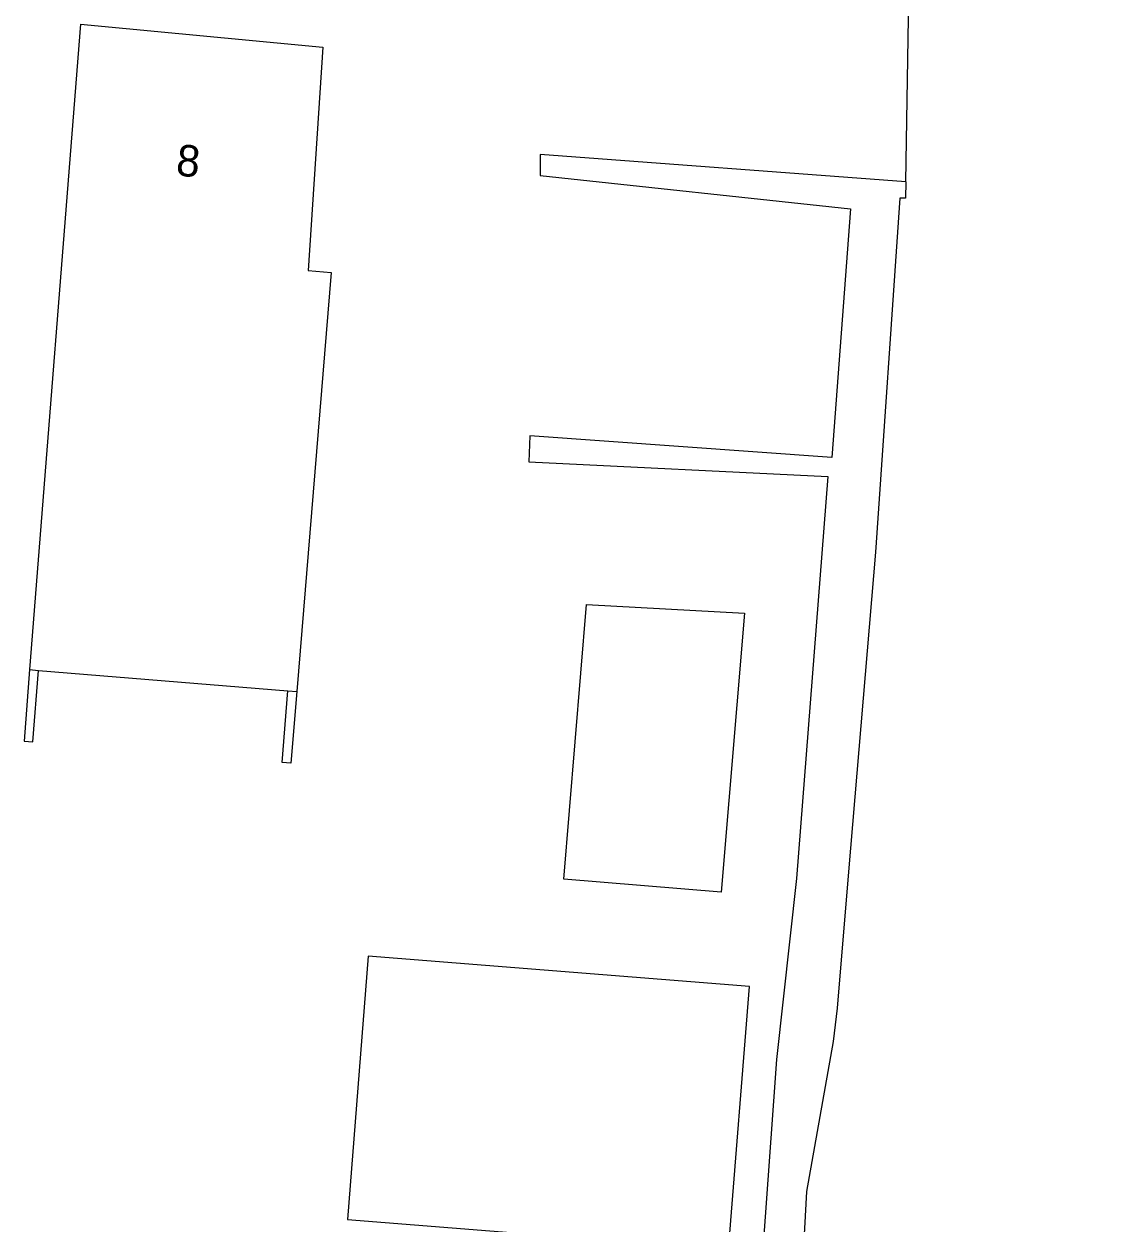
# Model space of a CAD drawing. Extents: x 137000 to 140001, y 403500 to 406000.
# Drawn here: x 138036.33 to 138070.55, y 405497.78 to 405535.89 of the extents above; entities that cross this region are included whole.
import ezdxf

# ---------------------------------------------------------------- set-up
doc = ezdxf.new("R2010")
doc.units = 0
for name, color, linetype in [('gg-afsc-muur', 7, 'Continuous'), ('gg-anno-huisnummerreeks BGT', 7, 'Continuous'), ('gg-bbg-bijgebouw', 7, 'Continuous'), ('gg-bbg-hoofdgebouw', 7, 'Continuous'), ('gg-knt-bronhoudergrens', 7, 'Continuous'), ('gt-grn-vlakafsluiter', 7, 'Continuous')]:
    doc.layers.add(name, color=color, linetype=linetype)

msp = doc.modelspace()

# ---------------------------------------------------------------- linework, layer by layer
at = {"layer": 'gg-afsc-muur'}
for points in [[(138036.508, 405515.388), (138036.329, 405513.115), (138036.608, 405513.093), (138036.787, 405515.365)], [(138044.987, 405514.69), (138044.8, 405512.418), (138044.521, 405512.441), (138044.708, 405514.713)]]:
    msp.add_lwpolyline(points, dxfattribs=at)
at = {"layer": 'gg-bbg-bijgebouw'}
for points in [[(138054.184, 405517.454), (138059.208, 405517.181), (138058.466, 405508.321), (138053.463, 405508.735), (138054.184, 405517.454)], [(138047.26, 405506.291), (138046.594, 405497.929), (138058.694, 405496.965), (138059.36, 405505.327), (138047.26, 405506.291)]]:
    msp.add_lwpolyline(points, dxfattribs=at)
at = {"layer": 'gg-bbg-hoofdgebouw'}
for p, q in [((138038.12, 405535.891), (138036.508, 405515.388)), ((138046.082, 405528.001), (138044.987, 405514.69)), ((138036.508, 405515.388), (138036.787, 405515.365)), ((138036.787, 405515.365), (138044.708, 405514.713)), ((138044.708, 405514.713), (138044.987, 405514.69))]:
    msp.add_line(p, q, dxfattribs=at)
msp.add_lwpolyline([(138038.12, 405535.891), (138045.811, 405535.161), (138045.352, 405528.062), (138046.082, 405528.001)], dxfattribs=at)
at = {"layer": 'gg-knt-bronhoudergrens'}
msp.add_line((138064.325, 405530.878), (138064.43, 405537.023), dxfattribs=at)
msp.add_lwpolyline([(138064.325, 405530.878), (138064.316, 405530.358), (138064.13, 405530.358), (138063.359, 405519.115), (138062.503, 405508.966), (138062.146, 405504.636), (138062.021, 405503.579), (138061.172, 405498.811), (138060.844, 405492.763), (138061.651, 405487.577)], dxfattribs=at)
at = {"layer": 'gt-grn-vlakafsluiter'}
msp.add_lwpolyline([(138064.325, 405530.878), (138052.716, 405531.744), (138052.716, 405531.082), (138062.572, 405530.024), (138061.976, 405522.12), (138052.385, 405522.814), (138052.352, 405521.987), (138061.844, 405521.524), (138060.852, 405508.758), (138060.223, 405503.003), (138059.76, 405496.687), (138059.529, 405492.949), (138060.19, 405489.41), (138060.422, 405486.831), (138050.434, 405487.757), (138050.5, 405490.27), (138050.037, 405490.27), (138049.971, 405487.393), (138061.885, 405486.073), (138061.948, 405485.671), (138070.553, 405485.595)], dxfattribs=at)

# ---------------------------------------------------------------- texts
at = {"layer": 'gg-anno-huisnummerreeks BGT'}
msp.add_text('8', height=1, rotation=354.6, dxfattribs=at).set_placement((138041.131, 405531.085))

doc.saveas('drawing.dxf')
